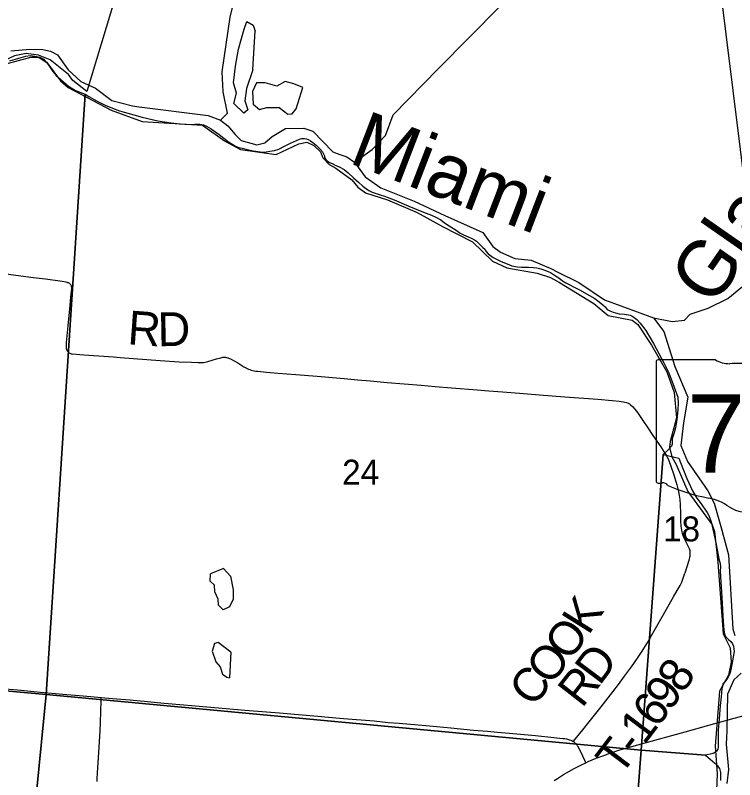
# Model space of a CAD drawing. Extents: x -19.5 to 44.1, y 0 to 22.
# Drawn here: x -17.865 to -16.656, y 15.7 to 16.984 of the extents above; entities that cross this region are included whole.
import ezdxf

# ---------------------------------------------------------------- set-up
doc = ezdxf.new("R2010")
doc.units = 0
for name, color, linetype in [('GM_X_County_Road', 7, 'Continuous'), ('GM_X_Major_River', 7, 'Continuous'), ('GM_X_Major_River_Text', 7, 'Continuous'), ('GM_X_Minor_Lake', 7, 'Continuous'), ('GM_X_Minor_River', 7, 'Continuous'), ('GM_X_Minor_River_Text', 7, 'Continuous'), ('GM_X_Section', 7, 'Continuous'), ('GM_X_Section_Text', 7, 'Continuous'), ('GM_X_State_Location', 7, 'Continuous'), ('GM_X_State_Shield', 7, 'Continuous'), ('GM_X_Township', 7, 'Continuous'), ('GM_X_Township_Road', 7, 'Continuous'), ('GM_X_Township_Road_Text', 7, 'Continuous'), ('GM_X_US_Route', 7, 'Continuous'), ('SH_Text', 7, 'Continuous')]:
    doc.layers.add(name, color=color, linetype=linetype)

msp = doc.modelspace()

# ---------------------------------------------------------------- linework, layer by layer
at = {"layer": 'GM_X_County_Road'}
for points in [[(-17.8887, 15.8531), (-17.8609, 15.8507), (-17.8226, 15.847), (-17.7848, 15.8437), (-17.7576, 15.8413), (-17.7378, 15.8396), (-17.7203, 15.838)], [(-17.7203, 15.838), (-17.7013, 15.8363), (-17.6716, 15.8337), (-17.6425, 15.8312), (-17.6144, 15.8285), (-17.5816, 15.8256), (-17.5429, 15.8222), (-17.5107, 15.8194), (-17.4789, 15.8168), (-17.4428, 15.8138), (-17.4209, 15.8119), (-17.3825, 15.8085), (-17.3565, 15.8065), (-17.3323, 15.8044), (-17.3131, 15.8027), (-17.2618, 15.7984), (-17.2383, 15.7961), (-17.2197, 15.7945), (-17.2005, 15.7929), (-17.1813, 15.7912), (-17.1566, 15.789), (-17.1331, 15.7868), (-17.0948, 15.7832), (-17.0712, 15.7811), (-17.0546, 15.7796), (-17.0218, 15.7766), (-16.9908, 15.7738), (-16.9601, 15.7707), (-16.9445, 15.7691), (-16.9414, 15.7687), (-16.9386, 15.7682), (-16.9369, 15.7677), (-16.9351, 15.7672), (-16.9334, 15.7666), (-16.9315, 15.7659), (-16.9292, 15.7648), (-16.9271, 15.7637)]]:
    msp.add_lwpolyline(points, dxfattribs=at)
at = {"layer": 'GM_X_Major_River'}
for points in [[(-17.8721, 16.9245), (-17.8405, 16.9273), (-17.8185, 16.927), (-17.8056, 16.9243), (-17.7937, 16.9178), (-17.7762, 16.8929), (-17.7548, 16.8732), (-17.7301, 16.8618), (-17.7027, 16.8412), (-17.668, 16.8325), (-17.6567, 16.8306), (-17.5405, 16.8159), (-17.5198, 16.808), (-17.5076, 16.7988), (-17.4951, 16.784), (-17.4852, 16.7742), (-17.4588, 16.7669), (-17.4454, 16.7699), (-17.4333, 16.7809), (-17.4109, 16.7939), (-17.3797, 16.7948), (-17.365, 16.7894), (-17.3315, 16.7552), (-17.3195, 16.7503), (-17.3075, 16.7465), (-17.2949, 16.7373), (-17.277, 16.7128), (-17.2507, 16.6945), (-17.1944, 16.6722), (-17.1431, 16.6477), (-17.0791, 16.6191), (-17.0623, 16.5957), (-17.0497, 16.5862), (-17.0254, 16.5756), (-16.9977, 16.5728), (-16.9651, 16.5588), (-16.9531, 16.5527), (-16.918, 16.5353), (-16.8745, 16.5061), (-16.7922, 16.4761), (-16.7747, 16.4528), (-16.7564, 16.3944), (-16.7345, 16.3427), (-16.742, 16.2996), (-16.7466, 16.2614), (-16.735, 16.2344), (-16.7008, 16.1854), (-16.6905, 16.1646), (-16.6792, 16.125), (-16.6663, 16.0779), (-16.6589, 15.9533), (-16.6558, 15.9418)], [(-17.8804, 16.9027), (-17.839, 16.9139), (-17.8253, 16.9139), (-17.8112, 16.9047), (-17.789, 16.8743), (-17.7761, 16.8633), (-17.7036, 16.8252), (-17.6517, 16.8061), (-17.5505, 16.7995), (-17.513, 16.7732), (-17.4865, 16.7586), (-17.4263, 16.7506), (-17.3881, 16.7684), (-17.3751, 16.7711), (-17.3631, 16.7657), (-17.3521, 16.7551), (-17.3482, 16.7447), (-17.3372, 16.7337), (-17.326, 16.7273), (-17.2992, 16.7078), (-17.289, 16.6953), (-17.2764, 16.6862), (-17.2391, 16.6744), (-17.1897, 16.653), (-17.1467, 16.6292), (-17.0963, 16.6037), (-17.0631, 16.5714), (-17.0388, 16.56), (-16.9881, 16.5512), (-16.9656, 16.5436), (-16.9503, 16.5351), (-16.8925, 16.5002), (-16.8684, 16.4801), (-16.8284, 16.472), (-16.8184, 16.4648), (-16.7956, 16.4299), (-16.7697, 16.3853), (-16.7575, 16.3503), (-16.7539, 16.308), (-16.7643, 16.268), (-16.7654, 16.2586), (-16.7617, 16.2421), (-16.7541, 16.2293), (-16.7347, 16.1842), (-16.6935, 16.1282), (-16.6897, 16.1166), (-16.6842, 16.0655), (-16.6755, 15.9447), (-16.6633, 15.9215), (-16.6618, 15.8975), (-16.6663, 15.8756), (-16.6816, 15.8483), (-16.6888, 15.7558), (-16.6853, 15.7093), (-16.6862, 15.6823)], [(-16.6449, 15.8787), (-16.6571, 15.8673), (-16.6681, 15.8437), (-16.6689, 15.7825), (-16.67, 15.7594), (-16.6661, 15.717), (-16.6691, 15.6932)]]:
    msp.add_lwpolyline(points, dxfattribs=at)
at = {"layer": 'GM_X_Minor_Lake'}
for points in [[(-17.4658, 16.8928), (-17.4763, 16.8615), (-17.479, 16.8406), (-17.474, 16.8257), (-17.4809, 16.8198), (-17.4977, 16.8361), (-17.4931, 16.8535), (-17.4981, 16.8711), (-17.4949, 16.8991), (-17.4898, 16.9275), (-17.4849, 16.9452), (-17.48, 16.9611), (-17.476, 16.9739), (-17.4651, 16.968), (-17.4615, 16.958)], [(-17.4658, 16.8928), (-17.4615, 16.9582)], [(-17.3814, 16.8629), (-17.3968, 16.8693), (-17.4115, 16.8734), (-17.4254, 16.8653), (-17.445, 16.8711), (-17.4594, 16.871), (-17.4661, 16.8563), (-17.465, 16.835), (-17.4546, 16.8261), (-17.4424, 16.8292), (-17.4215, 16.8295), (-17.4066, 16.8182), (-17.3997, 16.8188), (-17.3927, 16.8274)], [(-17.3927, 16.8274), (-17.3814, 16.8629)], [(-17.5148, 16.0545), (-17.5033, 16.0417), (-17.4988, 16.0189), (-17.4988, 16.0029), (-17.5047, 15.9905), (-17.5154, 15.9854), (-17.5236, 15.9932), (-17.5242, 16.0031), (-17.5293, 16.0153), (-17.5302, 16.0267), (-17.5372, 16.0334), (-17.537, 16.0459)], [(-17.5148, 16.0545), (-17.537, 16.0459)], [(-17.5028, 15.9141), (-17.5241, 15.9301), (-17.5302, 15.9287), (-17.5339, 15.9155), (-17.5281, 15.8979), (-17.5203, 15.8894), (-17.5164, 15.8771), (-17.5093, 15.872), (-17.5048, 15.8708)], [(-17.5028, 15.9141), (-17.5048, 15.8708)]]:
    msp.add_lwpolyline(points, dxfattribs=at)
at = {"layer": 'GM_X_Minor_River'}
for points in [[(-17.5198, 16.808), (-17.5082, 16.82), (-17.5155, 16.8555), (-17.5171, 16.8893), (-17.5035, 16.9814), (-17.4792, 17.0838), (-17.4703, 17.1509), (-17.4551, 17.2455), (-17.4679, 17.2933), (-17.472, 17.3318), (-17.4726, 17.3432), (-17.4605, 17.379), (-17.4583, 17.4016)], [(-17.2949, 16.7373), (-17.265, 16.7589), (-17.2426, 16.7824), (-17.2297, 16.8174), (-17.1535, 16.8948), (-17.0501, 16.9998)], [(-16.7922, 16.4761), (-16.761, 16.4696), (-16.7401, 16.4722), (-16.7308, 16.4823), (-16.7003, 16.4923), (-16.6673, 16.5083), (-16.6264, 16.5423)]]:
    msp.add_lwpolyline(points, dxfattribs=at)
at = {"layer": 'GM_X_Section'}
for points in [[(-17.8743, 16.9081), (-17.8587, 16.9124), (-17.8473, 16.916), (-17.8401, 16.9166), (-17.8318, 16.9157), (-17.8238, 16.9141), (-17.8171, 16.9106), (-17.8122, 16.9059), (-17.8074, 16.8983), (-17.8019, 16.8902), (-17.7963, 16.8833), (-17.7878, 16.876), (-17.7754, 16.8655), (-17.7635, 16.8581), (-17.7477, 16.8518), (-17.8129, 15.843), (-18.8417, 15.9351)], [(-17.9125, 14.8374), (-17.8129, 15.843), (-16.8129, 15.7495), (-16.8634, 15.0877)], [(-16.8634, 15.0877), (-16.8129, 15.7495), (-16.7052, 15.7408), (-16.6891, 15.7277), (-16.6854, 15.7234), (-16.6817, 15.7184), (-16.6795, 15.712), (-16.6798, 15.6983)]]:
    msp.add_lwpolyline(points, dxfattribs=at)
for points in [[(-17.2786, 16.6956), (-17.2748, 16.6929), (-17.2707, 16.6901), (-17.2654, 16.6874), (-17.2602, 16.6854), (-17.2519, 16.6826), (-17.2444, 16.6806), (-17.2282, 16.6742), (-17.2034, 16.6636), (-17.1786, 16.6537), (-17.1654, 16.6485), (-17.1579, 16.645), (-17.15, 16.6407), (-17.1437, 16.6357), (-17.1358, 16.6306), (-17.1242, 16.6232), (-17.1171, 16.6185), (-17.1114, 16.6154), (-17.1039, 16.6119), (-17.099, 16.6099), (-17.0934, 16.6068), (-17.09, 16.6048), (-17.0789, 16.594), (-17.0759, 16.5913), (-17.0737, 16.5875), (-17.0703, 16.5833), (-17.0617, 16.5771), (-17.0482, 16.5708), (-17.0381, 16.5668), (-17.0305, 16.5636), (-17.0211, 16.5616), (-17.0139, 16.5611), (-17.0018, 16.5613), (-16.9939, 16.5607), (-16.9886, 16.5599), (-16.9814, 16.5583), (-16.9724, 16.5551), (-16.9656, 16.5519), (-16.957, 16.5468), (-16.9514, 16.5433), (-16.945, 16.5383), (-16.9394, 16.5348), (-16.933, 16.5313), (-16.9267, 16.5281), (-16.9169, 16.523), (-16.9, 16.5133), (-16.891, 16.5082), (-16.8835, 16.5028), (-16.8776, 16.4978), (-16.8738, 16.4943), (-16.8701, 16.49), (-16.8668, 16.4881), (-16.863, 16.4865), (-16.86, 16.4853), (-16.8562, 16.4845), (-16.8502, 16.4829), (-16.8411, 16.482), (-16.8343, 16.4811), (-16.8317, 16.4803), (-16.829, 16.4795), (-16.8246, 16.4764), (-16.8204, 16.4729), (-16.8149, 16.4671), (-16.8052, 16.4548), (-16.7924, 16.433), (-16.7788, 16.4078), (-16.7751, 16.4002), (-16.7667, 16.3834), (-16.7577, 16.3597), (-16.7515, 16.3426), (-16.7509, 16.332), (-16.7515, 16.3221), (-16.7533, 16.3044), (-16.7542, 16.2976), (-16.7554, 16.2908), (-16.7575, 16.2829), (-16.7599, 16.2761), (-16.7611, 16.2727), (-16.7608, 16.2685), (-16.7612, 16.2636), (-16.762, 16.2602), (-16.7678, 16.2539), (-16.7759, 16.2464), (-16.8129, 15.7495), (-17.8129, 15.843), (-17.7477, 16.8518), (-17.7413, 16.8479), (-17.7274, 16.8401), (-17.7139, 16.8334), (-17.7015, 16.8283), (-17.6895, 16.8239), (-17.6518, 16.8134), (-17.6254, 16.8069), (-17.6031, 16.8035), (-17.5887, 16.8021), (-17.5713, 16.8006), (-17.563, 16.8012), (-17.5547, 16.8015), (-17.5486, 16.8002), (-17.5437, 16.7983), (-17.5359, 16.7936), (-17.5224, 16.7839), (-17.5067, 16.7715), (-17.4947, 16.7645), (-17.4891, 16.7621), (-17.4838, 16.7609), (-17.4747, 16.7588), (-17.4653, 16.7568), (-17.4536, 16.755), (-17.446, 16.7545), (-17.4369, 16.7559), (-17.4293, 16.7573), (-17.4221, 16.7594), (-17.4122, 16.7642), (-17.4026, 16.7697), (-17.387, 16.7762), (-17.3832, 16.7773), (-17.379, 16.7776), (-17.3756, 16.7768), (-17.3726, 16.7756), (-17.3688, 16.7736), (-17.3647, 16.7705), (-17.3591, 16.7659), (-17.3528, 16.7601), (-17.3487, 16.7547), (-17.3465, 16.7505), (-17.3454, 16.7482), (-17.3451, 16.7456), (-17.3429, 16.7421), (-17.341, 16.7398), (-17.3369, 16.7371), (-17.3324, 16.7351), (-17.3275, 16.7328), (-17.3207, 16.73), (-17.3121, 16.7253), (-17.3054, 16.7195), (-17.2965, 16.7114), (-17.2883, 16.7037), (-17.2808, 16.6971)], [(-16.6788, 15.8389), (-16.6802, 15.8244), (-16.6822, 15.8021), (-16.6836, 15.7828), (-16.6834, 15.7734), (-16.6837, 15.7541), (-16.6842, 15.7511), (-16.6865, 15.7477), (-16.6884, 15.7458), (-16.6911, 15.7444), (-16.6945, 15.7433), (-16.7052, 15.7408), (-16.8129, 15.7495), (-16.7759, 16.2464), (-16.7495, 16.2399), (-16.743, 16.2228), (-16.7365, 16.206), (-16.7266, 16.185), (-16.7207, 16.1747), (-16.7111, 16.1616), (-16.7048, 16.1528), (-16.7019, 16.149), (-16.6993, 16.144), (-16.6957, 16.133), (-16.6908, 16.1136), (-16.6869, 16.0949), (-16.6824, 16.071), (-16.6803, 16.063), (-16.68, 16.0577), (-16.6801, 16.0498), (-16.6775, 16.0065), (-16.6761, 15.9747), (-16.6739, 15.9508), (-16.6729, 15.9451), (-16.6714, 15.9405), (-16.6692, 15.9379), (-16.6662, 15.9352), (-16.6625, 15.9321), (-16.6595, 15.9282), (-16.6581, 15.924), (-16.6574, 15.9199), (-16.6567, 15.9149), (-16.658, 15.9089), (-16.6593, 15.8994), (-16.6622, 15.8843), (-16.6634, 15.8798), (-16.6654, 15.8753), (-16.6681, 15.8704), (-16.6708, 15.8663), (-16.6724, 15.8641), (-16.6758, 15.8607), (-16.6766, 15.8577), (-16.6775, 15.8524)], [(-18.8417, 15.9351), (-17.8129, 15.843), (-17.9125, 14.8374), (-18.924, 14.9235)]]:
    msp.add_lwpolyline(points, close=True, dxfattribs=at)
at = {"layer": 'GM_X_State_Shield'}
for p, q in [((-16.7878, 16.4019), (-16.7878, 16.2017)), ((-16.688, 16.4053), (-16.7845, 16.4053))]:
    msp.add_line(p, q, dxfattribs=at)
for centre, major_axis, start_param, end_param in [((-16.784, 16.4023), (0.00382, 0), 1.712693, 3.28349), ((-16.665, 16.4285), (0.037, 0), 4.042523, 4.731795), ((-16.6527, 16.2929), (0.133, 0), 1.404758, 1.657858), ((-16.7839, 16.2013), (0.00385, 0), 3.00124, 4.508301), ((-16.7834, 16.2218), (0.0294, 0), 4.665946, 4.897461), ((-16.7773, 16.1902), (0.0106, 0), 0.519207, 1.627899), ((-16.6435, 16.37), (0.2524, 0), 4.195997, 4.488961), ((-16.7188, 16.1118), (0.079, 0), 0.823519, 1.323587), ((-16.6334, 16.1892), (0.0501, 0), 4.026481, 4.996735)]:
    msp.add_ellipse(centre, major_axis=major_axis, ratio=0.8, start_param=start_param, end_param=end_param, dxfattribs=at)
at = {"layer": 'GM_X_Township'}
msp.add_lwpolyline([(-17.3561, 18.1443), (-17.4643, 17.7858), (-17.649, 17.1741), (-17.7449, 16.8564), (-17.7682, 16.8751), (-17.7757, 16.8847), (-17.8063, 16.9097), (-17.826, 16.9172), (-17.8465, 16.92), (-17.8664, 16.9161), (-17.9065, 16.8978), (-17.926, 16.8931), (-18.0112, 16.8966), (-18.0543, 16.8933), (-18.1184, 16.8749), (-18.1478, 16.8725), (-18.1785, 16.8797), (-18.2096, 16.8937), (-18.2423, 16.9001), (-18.7562, 16.9411), (-18.7834, 16.6305), (-18.8446, 15.9307), (-18.9306, 14.9193), (-19.0014, 14.1)], dxfattribs=at)
at = {"layer": 'GM_X_Township_Road'}
for points in [[(-17.8889, 16.5509), (-17.8344, 16.544), (-17.8141, 16.5414), (-17.7859, 16.5374), (-17.7799, 16.5365), (-17.7783, 16.5361), (-17.7769, 16.5356), (-17.7758, 16.5352), (-17.7748, 16.5347), (-17.7739, 16.534), (-17.7732, 16.5334), (-17.7725, 16.5328), (-17.772, 16.532), (-17.7715, 16.5313), (-17.7711, 16.5304), (-17.7708, 16.5295), (-17.7707, 16.5286), (-17.7706, 16.528), (-17.7705, 16.5273), (-17.7705, 16.5265), (-17.7705, 16.5255), (-17.7713, 16.5162), (-17.7736, 16.4908), (-17.7765, 16.4624), (-17.7793, 16.4346), (-17.7796, 16.429), (-17.7796, 16.4275), (-17.7795, 16.4259), (-17.7792, 16.4244), (-17.7788, 16.4229), (-17.7784, 16.4217), (-17.7778, 16.4206), (-17.7772, 16.4199), (-17.7766, 16.4192), (-17.7753, 16.418), (-17.7743, 16.4173), (-17.7732, 16.4166), (-17.7719, 16.4161), (-17.771, 16.4157), (-17.77, 16.4155), (-17.769, 16.4153), (-17.7495, 16.4139), (-17.7243, 16.412), (-17.6996, 16.4102), (-17.6884, 16.4094), (-17.6214, 16.4044), (-17.5894, 16.4022), (-17.5688, 16.4013), (-17.5577, 16.4009), (-17.5509, 16.4009), (-17.5483, 16.4011), (-17.546, 16.4014), (-17.5411, 16.4024), (-17.5269, 16.4068), (-17.5197, 16.409), (-17.518, 16.4094), (-17.5161, 16.4096), (-17.5146, 16.4097), (-17.513, 16.4098), (-17.5115, 16.4096), (-17.5099, 16.4094), (-17.5085, 16.409), (-17.5069, 16.4086), (-17.5061, 16.4082)], [(-17.5061, 16.4082), (-17.505, 16.4078), (-17.503, 16.4068), (-17.4911, 16.4001), (-17.4807, 16.3938), (-17.4771, 16.3918), (-17.4751, 16.3907), (-17.4727, 16.3896), (-17.4708, 16.3889), (-17.4686, 16.3882), (-17.4661, 16.3875), (-17.4632, 16.3869), (-17.4605, 16.3865), (-17.4577, 16.3861), (-17.4429, 16.3846), (-17.4237, 16.383), (-17.3933, 16.3808), (-17.3574, 16.3779), (-17.3123, 16.3739), (-17.29, 16.3717), (-17.2678, 16.3698), (-17.2401, 16.3675), (-17.1829, 16.3627), (-17.1594, 16.3608), (-17.1316, 16.3584), (-17.0888, 16.3548), (-17.069, 16.3533), (-17.0461, 16.3515), (-17.0176, 16.3493), (-16.9774, 16.3461), (-16.9415, 16.3433), (-16.8858, 16.3391), (-16.8616, 16.3372), (-16.8498, 16.336), (-16.8464, 16.3355), (-16.843, 16.335), (-16.8404, 16.3344), (-16.8377, 16.3334), (-16.835, 16.3323), (-16.8329, 16.3312), (-16.8311, 16.33), (-16.8278, 16.3272), (-16.8236, 16.3226), (-16.8191, 16.3167), (-16.81, 16.3034), (-16.8019, 16.2909), (-16.7932, 16.278), (-16.7801, 16.2591), (-16.7742, 16.2503), (-16.7702, 16.2433), (-16.7667, 16.2361), (-16.763, 16.2269), (-16.7585, 16.2139), (-16.7546, 16.2008), (-16.753, 16.1954), (-16.7515, 16.1888), (-16.7501, 16.1834), (-16.749, 16.1773), (-16.7481, 16.1705), (-16.7475, 16.1619), (-16.7472, 16.1482), (-16.7469, 16.1345), (-16.7463, 16.1259), (-16.7454, 16.1191), (-16.7448, 16.1161), (-16.7443, 16.1138), (-16.7435, 16.1114), (-16.7425, 16.109), (-16.7378, 16.0994), (-16.7322, 16.0882), (-16.7317, 16.0868), (-16.7313, 16.0847), (-16.7311, 16.0829), (-16.731, 16.0815), (-16.731, 16.08), (-16.7312, 16.0779), (-16.7314, 16.0751), (-16.7318, 16.073), (-16.7322, 16.0707), (-16.733, 16.068), (-16.7397, 16.0466)], [(-16.9271, 15.7637), (-16.9185, 15.7744), (-16.9088, 15.7865), (-16.9048, 15.7913), (-16.8805, 15.822), (-16.8607, 15.8475), (-16.8513, 15.8599), (-16.8408, 15.8738), (-16.8294, 15.8893), (-16.8191, 15.9041), (-16.8112, 15.916), (-16.8032, 15.9293), (-16.7914, 15.9498), (-16.7777, 15.9734), (-16.7659, 15.9939), (-16.7579, 16.0079), (-16.7494, 16.0231), (-16.7477, 16.0263), (-16.745, 16.0318), (-16.7424, 16.0386), (-16.7397, 16.0466)], [(-17.7271, 15.6968), (-17.7273, 15.7011), (-17.7266, 15.7115), (-17.7256, 15.7283), (-17.7225, 15.7814), (-17.7218, 15.7962), (-17.7205, 15.8322), (-17.7203, 15.838)], [(-16.9059, 15.7283), (-16.907, 15.7308), (-16.9151, 15.7478), (-16.917, 15.7517), (-16.9191, 15.7554), (-16.9199, 15.7567), (-16.9207, 15.7579), (-16.9215, 15.7589), (-16.9224, 15.7598), (-16.9234, 15.7608), (-16.9245, 15.7618), (-16.9258, 15.7628), (-16.9271, 15.7637)]]:
    msp.add_lwpolyline(points, dxfattribs=at)
at = {"layer": 'GM_X_US_Route'}
msp.add_lwpolyline([(-16.9595, 15.6982), (-16.9539, 15.7018), (-16.9434, 15.7084), (-16.9349, 15.7135), (-16.9257, 15.7186), (-16.9189, 15.722), (-16.9145, 15.7242), (-16.9059, 15.7283), (-16.9019, 15.7302), (-16.8886, 15.7358), (-16.876, 15.7406), (-16.8655, 15.7443), (-16.8505, 15.7492), (-16.8351, 15.7537), (-16.8124, 15.7599), (-16.7393, 15.7803), (-16.6992, 15.7913), (-16.6565, 15.8031), (-16.6378, 15.8083), (-16.6279, 15.8111), (-16.6253, 15.8118)], dxfattribs=at)
at = {"layer": 'SH_Text'}
msp.add_lwpolyline([(-16.7391, 19.8563), (-16.538, 15.8887), (-17.0308, 19.8566)], close=True, dxfattribs=at)

# ---------------------------------------------------------------- texts
at = {"layer": 'GM_X_Major_River_Text'}
msp.add_text('Miami', height=0.09469, rotation=338.9693, dxfattribs=at).set_placement((-17.3068, 16.7371))
at = {"layer": 'GM_X_Minor_River_Text'}
msp.add_text('Glady', height=0.09468, rotation=55.1514, dxfattribs=at).set_placement((-16.6924, 16.4919))
at = {"layer": 'GM_X_Section_Text'}
for s, p in [('24', (-17.3156, 16.1956)), ('18', (-16.7764, 16.1003))]:
    msp.add_text(s, height=0.04186, rotation=0, dxfattribs=at).set_placement(p)
at = {"layer": 'GM_X_State_Location'}
msp.add_text('725', height=0.000189, rotation=0, dxfattribs=at).set_placement((-16.6935, 16.2747))
at = {"layer": 'GM_X_State_Shield'}
msp.add_text('725', height=0.13184, dxfattribs=at).set_placement((-16.7362, 16.2158))
at = {"layer": 'GM_X_Township_Road_Text'}
for s, rotation, p in [('R', 355.8475, (-17.6772, 16.4317)), ('D', 1.0077, (-17.6252, 16.4281)), ('K', 57.8035, (-16.9013, 15.941)), ('O', 53.3964, (-16.9338, 15.897)), ('O', 51.8903, (-16.9657, 15.8563)), ('D', 53.1667, (-16.8829, 15.8565)), ('8', 55.3816, (-16.7433, 15.8429)), ('C', 51.8873, (-16.9945, 15.8196)), ('R', 52.0052, (-16.9124, 15.8187)), ('9', 53.4957, (-16.7653, 15.8131)), ('6', 53.0104, (-16.7866, 15.7847)), ('1', 52.8331, (-16.8079, 15.7567)), ('T', 52.777, (-16.8478, 15.7042)), ('-', 52.7784, (-16.8221, 15.738))]:
    msp.add_text(s, height=0.0568, rotation=rotation, dxfattribs=at).set_placement(p)

doc.saveas('drawing.dxf')
